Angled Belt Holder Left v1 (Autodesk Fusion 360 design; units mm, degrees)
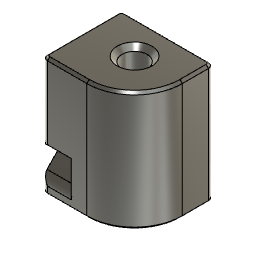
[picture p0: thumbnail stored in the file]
sketch "Sketch1" plane through (0, 0, 0) normal (0, 0, 1) x axis (1, 0, 0)
  line L1 (0, 16.5) -> (0, 0)
  line L2 (19.25, 16.5) -> (0, 16.5)
  line L3 (19.25, 10) -> (19.25, 16.5)
  line L4 (0, 0) -> (9.25, 0)
  arc A1 centre (9.25, 10) radius 10 clockwise from (19.25, 10) to (9.25, 0)
  circle C1 centre (9.75, 9.5) radius 2.625
  point P1 (0, 0)
  point P2 (0, 0)
  point P8 (0, 0)
  point P9 (9.75, 9.5)
  coincident P1 P2
  vertical L1
  perpendicular L1 L2
  perpendicular L2 L3
  tangent L3 A1
  perpendicular L3 L4
  tangent A1 L4
  coincident P1 P8
  dimension "d1" distance L2 L4 = 16.5
  dimension "d2" distance L1 L3 = 19.25
  dimension "d3" radius A1 = 10
  dimension "d6" distance L3 P9 = 9.5
  dimension "d7" distance L4 P9 = 9.5
  dimension "d8" diameter C1 = 5.25
extrude "Extrude1" new body sketch "Sketch1" along normal blind 25
work_plane "WorkPlane2" AlongDistance 0
sketch "Sketch3" plane through (0, 8.25, 12.5) normal (-1, 0, 0) x axis (0, 1, 0)
  line L1 (-8.25, 12.5) -> (8.25, 12.5)
  line L2 (-8.25, -12.5) -> (-8.25, 12.5)
  line L3 (8.25, -12.5) -> (-8.25, -12.5)
  line L4 (8.25, 12.5) -> (8.25, -12.5)
  line L5 (-5.949, 1.5421) -> (-8.25, 3.8431)
  line L6 (-8.25, 9.5) -> (-4.4653, 5.7153)
  arc A1 centre (-7.3632, 0.1279) radius 2 clockwise from (-5.949, 1.5421) to (-5.5224, -0.6541)
  arc A2 centre (0, -3) radius 6 clockwise from (0.9772, 2.9199) to (-5.5224, -0.6541)
  arc A3 centre (2.6057, 12.7864) radius 10 clockwise from (0.9772, 2.9199) to (-4.4653, 5.7153)
  circle C1 centre (0, -3) radius 2
  arc A4 centre (-8, 3.2396) radius 0.25 clockwise from (-8.25, 3.2396) to (-7.8232, 3.4164)
  arc A5 centre (-5.25, 10.7426) radius 3 clockwise from (-7.3713, 8.6213) to (-8.25, 10.7426)
  point P6 (-8.25, 3.8431)
  point P14 (-8.25, 9.5)
  point P1 (0, 0)
  point P11 (0, -3)
  point P17 (-8.25, 3.2396)
  point P16 (-7.8232, 3.4164)
  point P20 (-8.25, 10.7426)
  point P19 (-7.3713, 8.6213)
  point P3 (-8.25, 12.5)
  coincident L2 P6
  tangent L5 A1
  tangent A1 A2
  tangent A2 A3
  tangent A3 L6
  coincident L2 P14
  parallel L5 L6
  vertical P1 P11
  concentric A2 C1
  tangent L2 A4
  coincident L2 P17
  coincident L5 P16
  tangent L5 A4
  tangent L2 A5
  coincident L2 P20
  coincident L6 P19
  tangent L6 A5
  dimension "d14" radius A3 = 10
  dimension "d15" radius A1 = 2
  dimension "d16" distance L5 L6 = 4
  dimension "d18" distance P3 P14 = 3
  dimension "d19" distance P1 P11 = 3
  dimension "d20" angle L1 L6 = 45
  dimension "d21" diameter C1 = 4
  dimension "d22" distance A2 C1 = 4 (= "d16")
  dimension "d25" radius A4 = 0.25
  dimension "d26" radius A5 = 3
extrude "Extrude2" cut sketch "Sketch3" profile of L2 L5 A1 A2 A3 L6 C1 A4 A5 against normal blind 6
fillet "Fillet2" radius 1
chamfer "Chamfer3" distance 0.5
chamfer "Chamfer4" distance 1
